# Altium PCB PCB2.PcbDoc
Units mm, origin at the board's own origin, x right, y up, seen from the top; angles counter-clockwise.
Board outline 88.49 x 68.81 mm, 2 copper layers (Top Layer, Bottom Layer); 19 components, 14 nets, 71 pads, 0 vias.
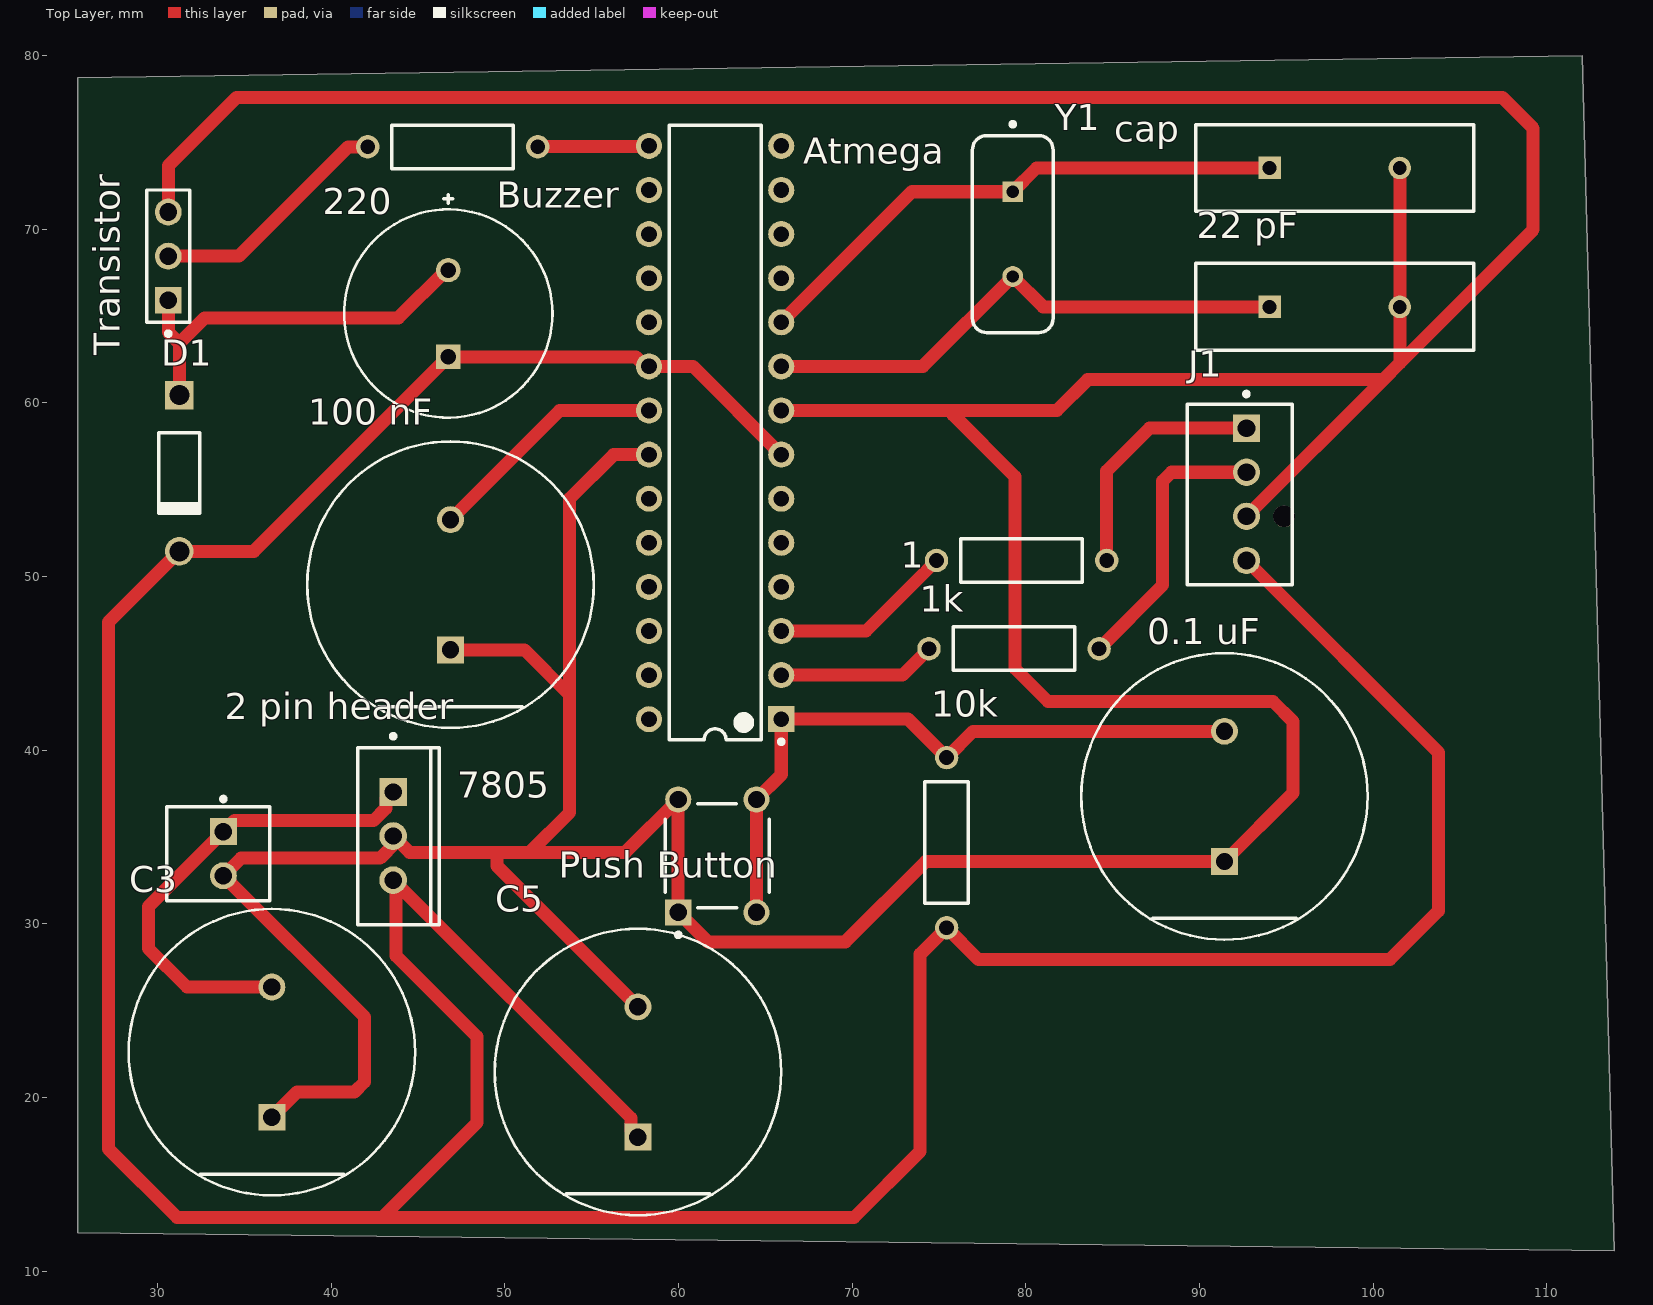
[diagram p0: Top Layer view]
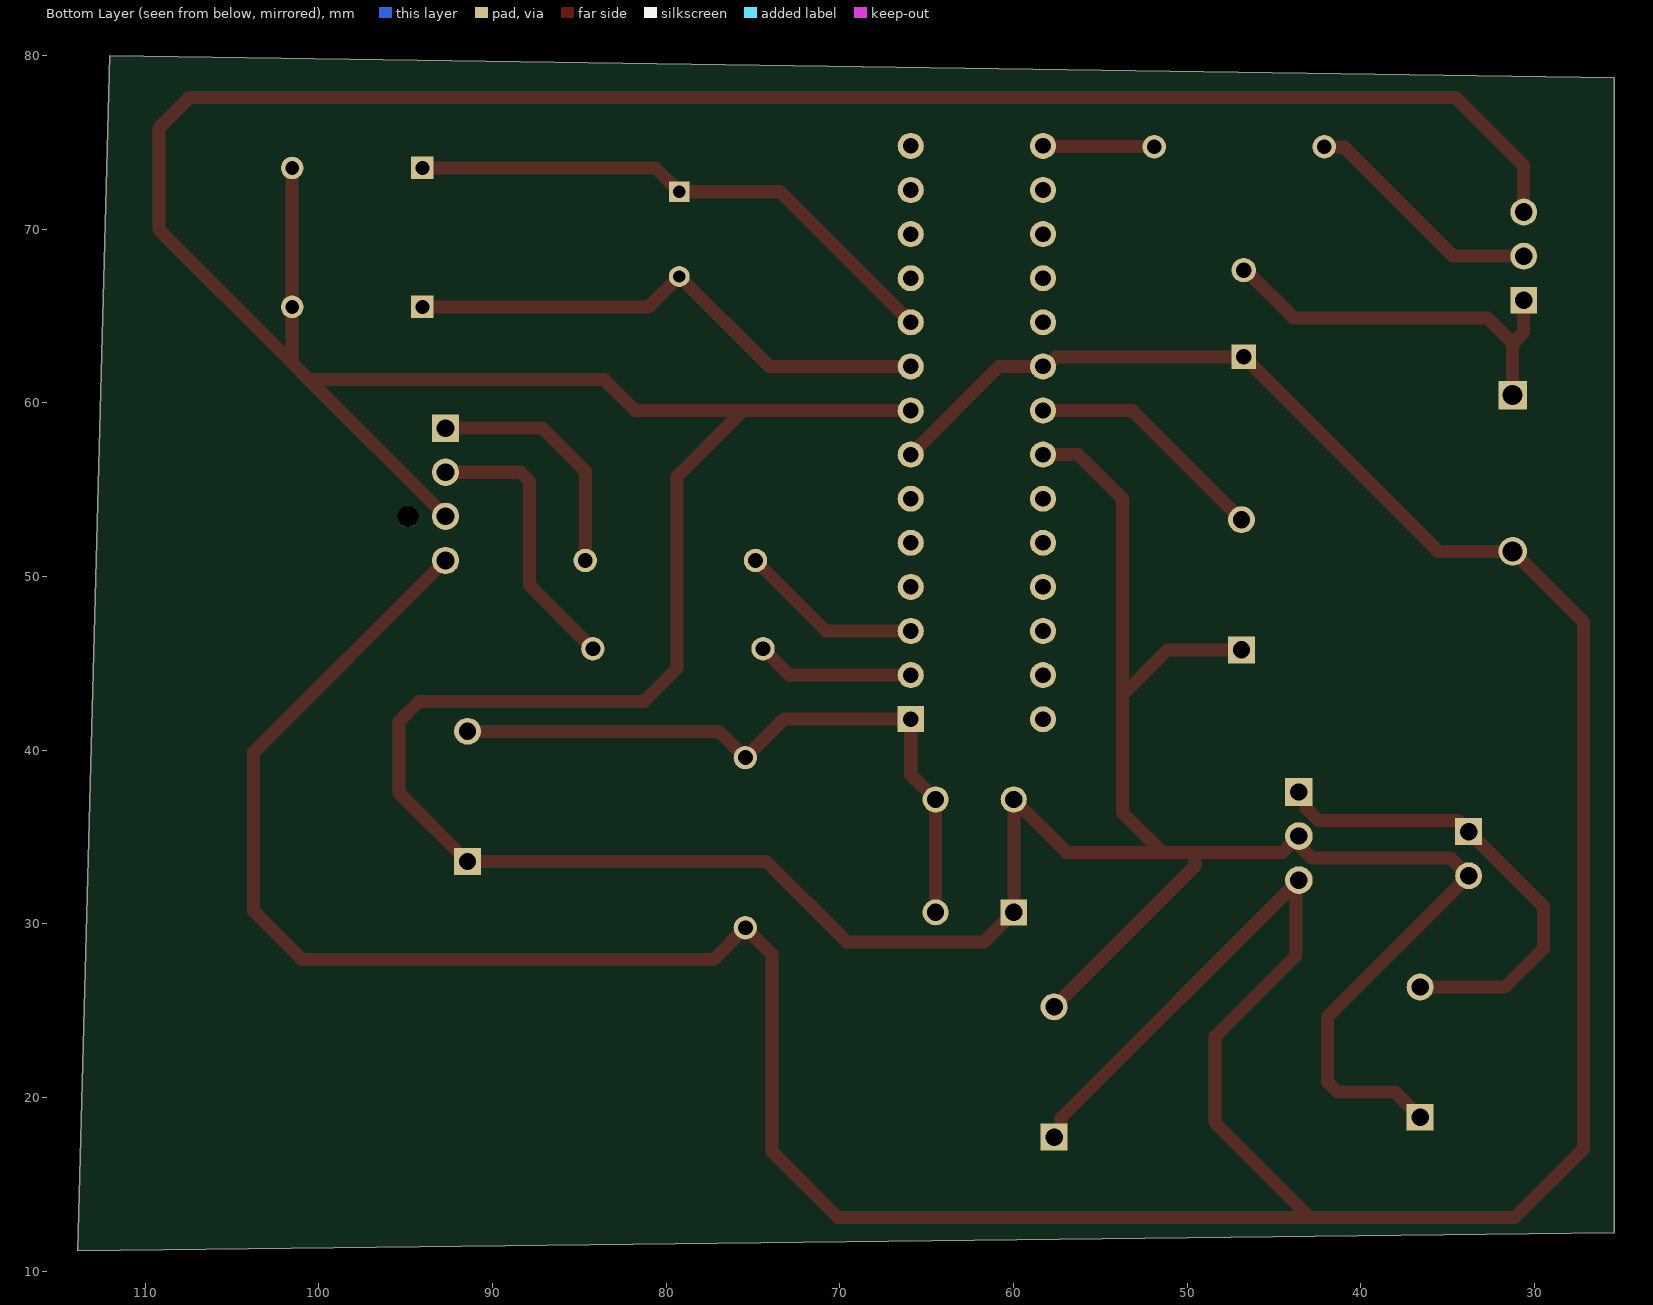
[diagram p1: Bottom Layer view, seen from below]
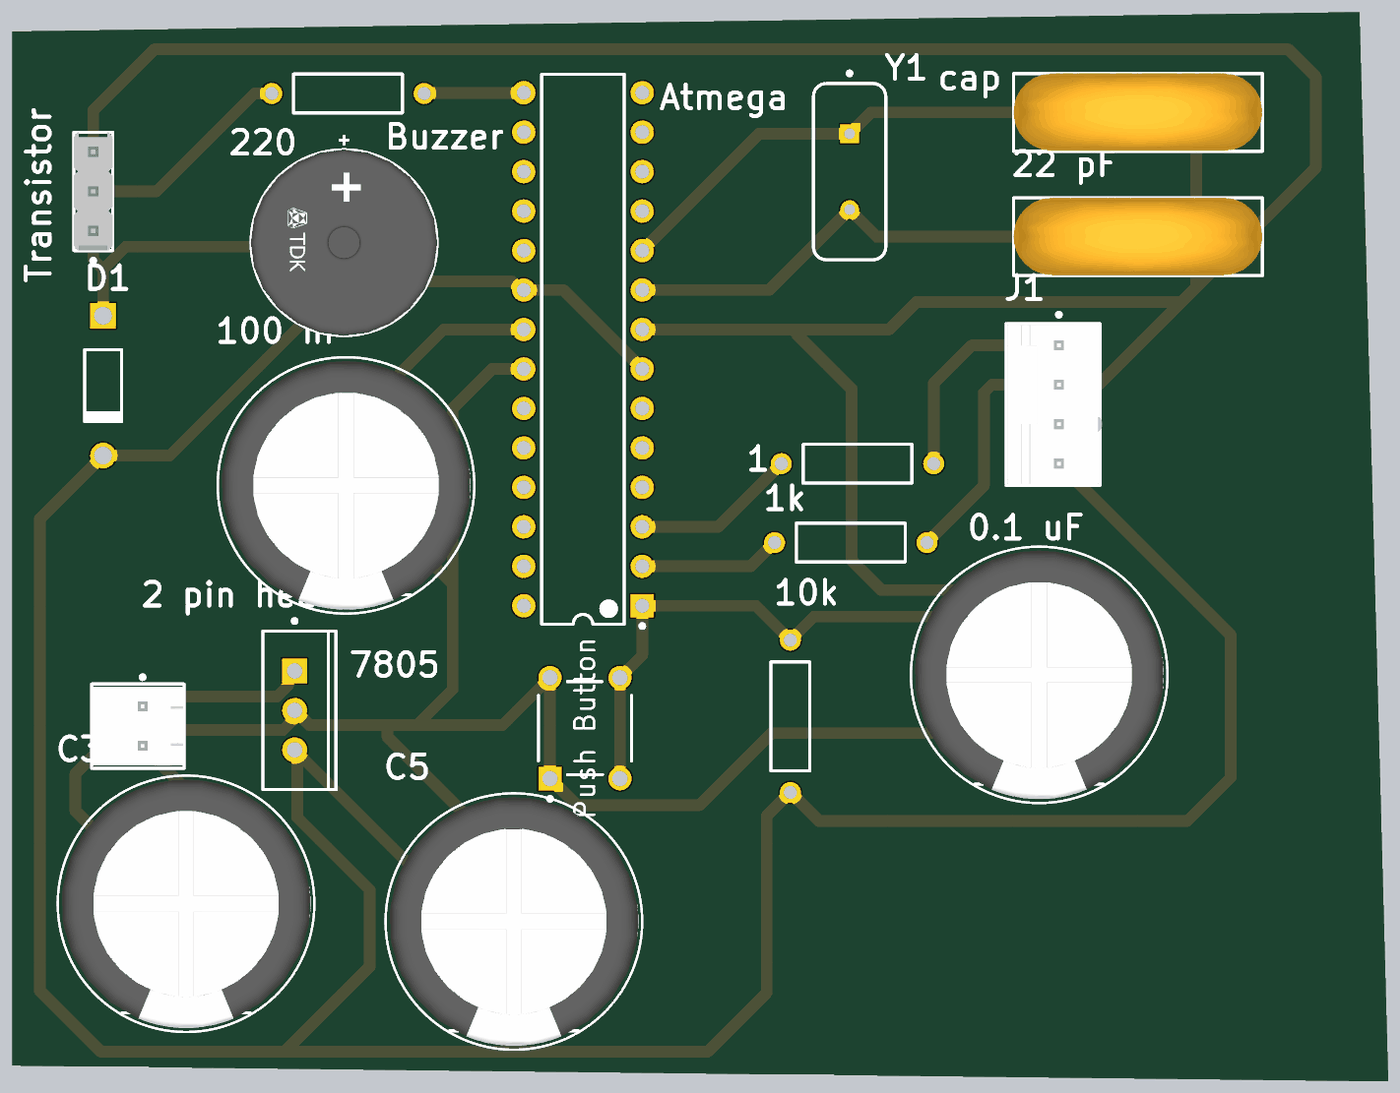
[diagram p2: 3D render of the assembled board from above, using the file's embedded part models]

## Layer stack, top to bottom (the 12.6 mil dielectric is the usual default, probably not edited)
Top Solder: solder mask 0.0102, Solder Resist, Dk 3.5
Top Layer: signal copper 0.0356
Dielectric 1: dielectric 0.32, FR-4, Dk 4.8
Bottom Layer: signal copper 0.0356
Bottom Solder: solder mask 0.0102, Solder Resist, Dk 3.5

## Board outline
25.4,12.192 113.885,11.175 112.037,79.99 25.4,78.74

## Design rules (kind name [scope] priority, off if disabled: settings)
Clearance [All] p1: gap=0.254 ignorepadtopadclearanceinfootprint=FALSE except(0: Arc-Hole Track-Hole SMDPad-Hole THPad-Hole Via-Hole Fill-Hole Poly-Hole Region-Hole Text-Hole)
PolygonConnect [All] p1: connectstyle=Relief reliefconductorwidth=0.254 reliefentries=4 polygonreliefangle="90 Angle" airgapwidth=0.254
RoutingVias [All] p1: holewidth=0.711 width=1.27 viastyle="Through Hole" minholewidth=0.711 minwidth=1.27 maxholewidth=0.711 maxwidth=1.27
SolderMaskExpansion [All] p1: expansion=0.102 istentingtop=FALSE
Width [All] p1: maxlimit=1 minlimit=0.7 preferedwidth=0.75
30 further rules are at their usual default settings.

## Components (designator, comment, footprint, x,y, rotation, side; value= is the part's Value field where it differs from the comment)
"0.1 uF" "EEUEE2G470" FP-RAD-TH-D_16_0_5-L_25_2-MFG 91.44,37.338 r90 top
1 "OD103JE" OMTE-RES7X2.5-2 79.756,50.927 r0 top
1k "OD103JE" OMTE-RES7X2.5-2 79.322,45.847 r0 top
"2 pin header" "61900211121" FP-61900211121-MFG 33.482,34.036 r270 top
10k "OD103JE" OMTE-RES7X2.5-2 75.438,34.671 r90 top
"22 pF" "VY2103M63Y5US63V7" FP-VY2103M63Y5US63V7-MFG 97.79,65.532 r0 top
"100 nF" "EEUEE2G470" FP-RAD-TH-D_16_0_5-L_25_2-MFG 46.863,49.53 r90 top
220 "OD103JE" OMTE-RES7X2.5-2 46.99,74.75 r180 top
7805 "LM7805CT" FAIR-TO-220-3 43.561,35.052 r0 top
Atmega "ATmega328-PU" 28P3 62.103,58.293 r180 top
Buzzer "SD1209T5-A1" FP-SD1209-MFG 46.736,65.151 r90 top
C3 "0.33 uF" FP-RAD-TH-D_16_0_5-L_25_2-MFG 36.576,22.606 r90 top
C5 "0.1 uF" FP-RAD-TH-D_16_0_5-L_25_2-MFG 57.658,21.463 r90 top
cap "VY2103M63Y5US63V7" FP-VY2103M63Y5US63V7-MFG 97.79,73.533 r0 top
D1 "1N4001-T" DIOD-DO-41-P-2_V 31.242,55.952 r270 top
J1 "47053-3000" FP-47053-3000-MFG 92.33,54.737 r90 top
"Push Button" "1825910-6" TECO-1825910-6_V 62.23,33.909 r90 top
Transistor "22-28-4033" MOLX-22-28-4033_V 30.607,68.453 r90 top
Y1 "FOXSLF/160-20" FOX-FOXSLF160-20 79.248,69.723 r270 top

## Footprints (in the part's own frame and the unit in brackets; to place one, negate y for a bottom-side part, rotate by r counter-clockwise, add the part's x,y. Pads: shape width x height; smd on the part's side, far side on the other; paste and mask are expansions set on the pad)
28P3 [mm] "28-Pin Plastic Dual In-Line Package (PDIP)"
  rect 1.5x1.5 hole 0.9: 1(-3.81,16.51)
  round 1.5 hole 0.9: 2(-3.81,13.97) 3(-3.81,11.43) 4(-3.81,8.89) 5(-3.81,6.35) 6(-3.81,3.81) 7(-3.81,1.27) 8(-3.81,-1.27) 9(-3.81,-3.81) 10(-3.81,-6.35) 11(-3.81,-8.89) 12(-3.81,-11.43) 13(-3.81,-13.97) 14(-3.81,-16.51) 15(3.81,-16.51) 16(3.81,-13.97) 17(3.81,-11.43) 18(3.81,-8.89) 19(3.81,-6.35) 20(3.81,-3.81) 21(3.81,-1.27) 22(3.81,1.27) 23(3.81,3.81) 24(3.81,6.35) 25(3.81,8.89) 26(3.81,11.43) 27(3.81,13.97) 28(3.81,16.51)
  silkscreen extent -3.94,-17.7 2.65,17.93, body extent -3.6,-17.65 3.6,17.65, height 4.58
DIOD-DO-41-P-2_V [mm] "2-Leads, Axial Lead, Body 4.635x2.36mm, Pin Spacing 9mm"
  rect 1.65x1.65 hole 1.15: 1(-4.5,0)
  round 1.65 hole 1.15: 2(4.5,0)
  silkscreen extent -2.32,-1.18 2.32,1.18, body extent -4.93,-1.18 4.93,1.18, height 2.35
FAIR-TO-220-3 [mm] "FM, 3-Leads, Body 10.2x4.7mm, Pitch 2.54mm"
  rect 1.6x1.6 hole 1: 1(0,2.54)
  round 1.6 hole 1: 2(0,0) 3(0,-2.54)
  silkscreen extent -2.04,-5.1 2.66,5.87, body extent -2.04,-5.1 2.66,5.1, height 18.95
FOX-FOXSLF160-20 [mm] "THD, 2-Leads, Body 11.35x4.65mm"
  rect 1.2x1.2 hole 0.7: 1(-2.44,0)
  round 1.2 hole 0.7: 2(2.44,0)
  silkscreen extent -6.45,-2.32 5.68,2.32, body extent -5.67,-2.32 5.68,2.33, height 3.6
FP-47053-3000-MFG [mm]
  rect 1.57x1.57 hole 1.02 paste-1000 mask+0: 1(3.81,-0.38)
  round 1.57 hole 1.02 paste-1000 mask+0: 2(1.27,-0.38) 3(-1.27,-0.38) 4(-3.81,-0.38)
  round 1.25 hole 1.25 unplated paste-1000 mask+0: ""(-1.27,-2.54)
  silkscreen extent -5.2,-3.02 5.9,3.02, body extent -5.3,-3.26 5.3,3.12, height 0.25
FP-61900211121-MFG [mm]
  rect 1.55x1.55 hole 1 paste-1000 mask+0: 1(-1.27,0.3)
  round 1.55 hole 1 paste-1000 mask+0: 2(1.27,0.3)
  silkscreen extent -3.27,-2.98 2.71,2.98, body extent -2.81,-3.08 2.81,3.08, height 0.25
FP-RAD-TH-D_16_0_5-L_25_2-MFG [mm]
  rect 1.55x1.55 hole 1 paste-1000 mask+0: 1(-3.75,0)
  round 1.55 hole 1 paste-1000 mask+0: 2(3.75,0)
  silkscreen extent -8.25,-8.25 8.25,8.25, body extent -8.35,-8.35 8.35,8.35, height 0.25
FP-SD1209-MFG [mm]
  rect 1.4x1.4 hole 0.9 paste-1000 mask+0: 1(-2.5,0)
  round 1.4 hole 0.9 paste-1000 mask+0: 2(2.5,0)
  silkscreen extent -6,-6 6.85,6, body extent -6.1,-6.1 6.1,6.1, height 0.25
FP-VY2103M63Y5US63V7-MFG [mm]
  rect 1.3x1.3 hole 0.8 paste-1000 mask+0: 1(-3.75,0)
  round 1.3 hole 0.8 paste-1000 mask+0: 2(3.75,0)
  silkscreen extent -8,-2.5 8,2.5, body extent -8.1,-2.6 8.1,2.6, height 0.25
MOLX-22-28-4033_V [mm] "THD, 3-Leads, Body 7.62x2.49mm, Pitch 2.54mm"
  rect 1.55x1.55 hole 1.02: 1(-2.54,0)
  round 1.55 hole 1.02: 2(0,0) 3(2.54,0)
  silkscreen extent -4.58,-1.24 3.81,1.24, body extent -3.81,-1.24 3.81,1.24, height 8.38
OMTE-RES7X2.5-2 [mm] "Resistor, Axial; Body 7x2.5mm, Lead Dia. 0.6mm"
  round 1.35 hole 0.85: 1(-4.9,0) 2(4.9,0)
  silkscreen extent -3.5,-1.25 3.5,1.25, body extent -3.5,-1.25 3.5,1.25, height 2.5
TECO-1825910-6_V [mm] "Switch, 4-Leads, Body 5.99x5.99mm"
  rect 1.5x1.5 hole 0.99: 1(-3.25,2.25)
  round 1.5 hole 0.99: 2(3.25,2.25) 3(-3.25,-2.25) 4(3.25,-2.25)
  silkscreen extent -4.67,-2.99 2.99,3, body extent -3,-2.99 2.99,3, height 5

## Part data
"0.1 uF" "100 nF" C3 C5: library part CMP-05427-001116-1, "Aluminum Electrolytic Capacitors (Radial Lead Type) 47uF ±20% 400V", Capacitance=47uF, Case/Package=Radial, Dielectric Material=Aluminium, Leakage Current=1.138mA, Max Operating Temperature=105°C, Min Operating Temperature=-25°C, Package Quantity=100, Ripple Current=1.18A, Tolerance=20%, Voltage=400V
1 1k 10k 220: library part CMP-2000-06865-1, "Little Demon(R) Carbon Composition Molded OD Series, 250 V, 10 KOhm, +/-5%, -70 to 130 degC, 2-Pin THD, RoHS, Bulk", Manufacturer=Ohmite, Operating Temperature=-, Package / Case=Axial, Package Description="2-Pin THD Resistor, Body 7 x 2.5 mm, Lead Dia. 0.6 mm", Package Reference=RES7X2.5, Power (Watts)=0.25W,1/4W, Power Rating=0.25W, Resistance (Ohms)=10k, Standard Package=100, Tolerance=±5%
"2 pin header": library part CMP-1502-00584-2, "CONN HEADER VERT 2POS 2.54MM", Color=Beige, Current Rating=3A, Flammability Rating="UL94 V-0", Insulation Resistance=1GR, Max Operating Temperature=105°C, Min Operating Temperature=-40°C, Package Quantity=1000, Voltage Rating=250V
"22 pF" cap: library part CMP-02417-000049-1, "CAP CER 10000PF 440VAC Y5U RDL", Capacitance=10nF, Case/Package=Radial, Dielectric=Y5U, Max Operating Temperature=125°C, Min Operating Temperature=-40°C, Package Quantity=500, Resistor Type=Ceramic, Tolerance=20%, Voltage Rating (AC)=300V
7805: library part CMP-2000-04938-1, "Positive Voltage Regulator, 5 V, 1 A, -40 to 125 degC, 3-Pin TO-220, RoHS, Tube", Manufacturer=FairchildSemiconductor, Maximum Input Voltage=35V, Maximum Output Current=2.2(Typ)A, Maximum Quiescent Current=8mA, Operating Temperature=-40to125degC, Output Voltage=5V, Package=3TO-220AB, Package Description="3-Pin Through Hole Device, Body 10 x 4.5 mm, Pitch 2.54 mm", Package Reference=TO-220, Typical Dropout Voltage @ Current=2@1AV
Atmega: library part CMP-0095-00015-2, "8-bit AVR Microcontroller, 32KB Flash, 1KB EEPROM, 2KB SRAM, 28-pin PDIP, Industrial Grade (-40°C to 85°C)"
Buzzer: library part CMP-08413-000009-1, "AUDIO MAGNETIC XDCR 3-6V TH", Current Rating=60mA, Frequency=2.048kHz, Max Operating Temperature=85°C, Min Operating Temperature=-40°C, Operating Supply Voltage=5V, Package Quantity=100, Self Resonant Frequency=2.05kHz
D1: library part CMP-0639-00006-2, "1.0 A Rectifier, 15 pF, 50 V, -65 to 150 degC, 2-Pin DO-41 Plastic, RoHS, Tape and Reel", Manufacturer="Diodes Inc", Max. Average Rectified Current IO (A)=1, Operating Temperature Range (degC)="-65 to 150"
J1: library part CMP-04776-000447-1, "CONN HEADER VERT 4POS 2.54MM", Current Rating=4A, Max Operating Temperature=75°C, Min Operating Temperature=0°C, Package Quantity=12000, Voltage Rating=250V
"Push Button": library part CMP-1684-00021-1, "Tact Switch, SPST-NO, 0.05 A, -35 to 85 degC, 4-Pin THD, RoHS, Bulk", Actuator Color=Black, Contact Rating @ Voltage=0.05A@24VDC, Dielectric Strength=500VAC, Manufacturer="TE Connectivity", Maximum AC Voltage Rating=N/A, Maximum Contact Resistance=100mOhm, Maximum DC Voltage Rating=24V, Minimum Insulation Resistance=100MOhm, Operating Temperature=-35to85C, Package Description="4-Pin Through Hole Device, Body 5.99 x 5.99 mm, Pitch 6.5 mm", Package Reference=THD
Transistor: library part CMP-1676-00001-5, "Male Header, Pitch 2.54 mm, 1 x 3 Position, Height 8.38 mm, Tail Length 3.18 mm, RoHS, Bulk", Colour=Black, Current Rating="4 A", Manufacturer=Molex, Max Operating Temperature="75 degC", Min Operating Temperature="0 degC", Package Quantity=1, Voltage Rating="250 V"
Y1: library part CMP-1749-00003-1, "Resistance Weld Thru-Hole Crystal, 16 MHz, -20 to 70 degC, 2-Pin THD, RoHS, Bulk", Case\Package=Axial, Max Operating Temperature="155 degC", Min Operating Temperature="-55 degC", Package Quantity=200, Power Rating="250 mW", Resistance="221 kohm", Tolerance=1%, Voltage Rating="250 V"

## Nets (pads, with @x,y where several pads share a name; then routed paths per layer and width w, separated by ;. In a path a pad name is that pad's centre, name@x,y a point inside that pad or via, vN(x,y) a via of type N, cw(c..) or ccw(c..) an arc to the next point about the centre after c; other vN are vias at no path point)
+5: 10k.1 7805.3 Atmega.7 Atmega.20 Buzzer.1 C5.1 D1.2 J1.4 | length 240.4
  Top Layer w0.75: 7805.3 57.258,18.815 57.258,18.113 C5.1 ; 7805.3@43.724,32.119 43.724,28.158 48.387,23.495 48.387,18.542 42.926,13.081 ; Atmega.7 60.833,62.103 Atmega.20 58.09,62.103 57.542,62.651 46.95,62.651 46.736,62.865 Buzzer.1 35.537,51.452 D1.2 27.178,47.388 27.178,17.018 31.115,13.081 42.926,13.081 ; J1.4 103.759,39.878 103.759,30.734 100.965,27.94 77.269,27.94 10k.1 73.914,28.247 73.914,16.891 70.104,13.081 42.926,13.081
GND: 7805.2 "0.1 uF.1" "2 pin header.2" "22 pF.2" "100 nF.1" "Push Button.1" "Push Button.2" Atmega.8 Atmega.22 C3.1 C5.2 cap.2 J1.3 Transistor.3 | length 340.7
  Top Layer w0.75: Transistor.3 30.607,73.66 34.544,77.597 107.442,77.597 109.22,75.819 109.22,69.977 101.54,62.297 ; C3.1 38.037,20.317 41.34,20.317 41.91,20.886 41.91,24.638 33.782,32.766 34.798,33.782 42.81,33.782 7805.2@43.709,34.681 ; 7805.2 44.503,34.11 49.53,34.11 ; 46.863,45.78 51.121,45.78 53.721,43.18 ; C5.2 49.53,33.341 49.53,34.11 ; Atmega.22 56.261,57.023 53.721,54.483 53.721,43.18 ; Atmega.8 75.819,59.563 ; J1.3 100.584,61.341 ; cap.2 101.54,65.532 101.54,62.297 ; 49.53,34.11 51.435,34.11 ; 51.435,34.11 53.721,36.396 53.721,43.18 ; 51.435,34.11 56.931,34.11 59.98,37.159 59.98,30.659 61.683,28.956 69.603,28.956 74.235,33.588 91.44,33.588 95.377,37.525 95.377,41.656 94.234,42.799 81.28,42.799 79.375,44.704 79.375,55.753 75.819,59.309 75.819,59.563 ; 75.819,59.563 81.788,59.563 83.566,61.341 100.584,61.341 ; 100.584,61.341 101.54,62.297
Net1_1: 1.1 Atmega.3 | length 10.6
  Top Layer w0.75: Atmega.3 70.792,46.863 1.1
Net1k_1: 1k.1 Atmega.2 | length 9.1
  Top Layer w0.75: Atmega.2 72.898,44.323 1k.1
"Net2 pin header_1": 7805.1 "2 pin header.1" C3.2 | length 27.8
  Top Layer w0.75: C3.2 31.683,26.356 29.464,28.575 29.464,30.988 33.782,35.306 34.417,35.941 42.429,35.941 43.136,36.648 43.136,37.167 43.154,37.185 7805.1@43.968,37.185
"Net22 pF_1": "22 pF.1" Atmega.9 Y1.2 | length 31
  Top Layer w0.75: Atmega.9 74.068,62.103 Y1.2 80.999,65.532 94.04,65.532
"Net100 nF_2": "100 nF.2" Atmega.21 | length 14
  Top Layer w0.75: 46.863,53.28 53.146,59.563 Atmega.21
Net220_2: 220.2 Transistor.2 | length 14.1
  Top Layer w0.75: Transistor.2 34.671,68.453 40.968,74.75 220.2
NetAtmega_10: Atmega.10 cap.1 Y1.1 | length 31.8
  Top Layer w0.75: Atmega.10 73.433,72.163 Y1.1 80.618,73.533 cap.1
NetBuzzer_2: Buzzer.2 D1.1 Transistor.1 | length 23
  Top Layer w0.75: Transistor.1 30.607,64.072 31.242,63.436 ; D1.1 31.242,63.436 ; Buzzer.2 46.615,67.651 43.861,64.897 32.703,64.897 31.242,63.436
NetLabel1: 10k.2 "0.1 uF.2" "Push Button.3" "Push Button.4" Atmega.1 | length 38.8
  Top Layer w0.75: 64.48,30.659 64.48,37.159 65.913,38.592 Atmega.1 73.226,41.783 10k.2 76.955,41.088 91.44,41.088
NetLabel2: 1k.2 J1.2 | length 16.2
  Top Layer w0.75: 1k.2 87.884,49.509 87.884,55.499 88.392,56.007 J1.2
NetLabel3: 1.2 J1.1 | length 14.2
  Top Layer w0.75: 1.2 84.656,56.081 87.122,58.547 J1.1
NetLabel4: 220.1 Atmega.15 | length 6.4
  Top Layer w0.75: 220.1 51.917,74.777 58.267,74.777 Atmega.15
pads on no net: Atmega.4 Atmega.5 Atmega.6 Atmega.11 Atmega.12 Atmega.13 Atmega.14 Atmega.16 Atmega.17 Atmega.18 Atmega.19 Atmega.23 Atmega.24 Atmega.25 Atmega.26 Atmega.27 Atmega.28 J1.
